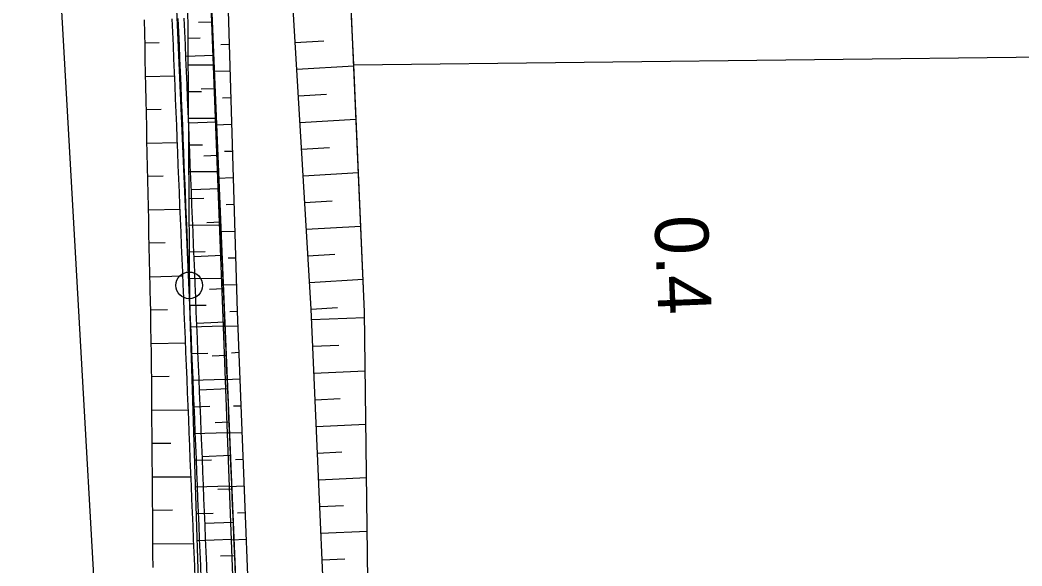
# Model space of a CAD drawing. Extents: x -583721 to -583071, y -1166145 to -1165065.
# Drawn here: x -583239 to -583164, y -1165749.9 to -1165709.1 of the extents above; entities that cross this region are included whole.
import ezdxf

# ---------------------------------------------------------------- set-up
doc = ezdxf.new("R2010")
doc.units = 0
for name, color, linetype in [('01_DOPRAVA', 7, 'Continuous'), ('14', 7, 'Continuous'), ('21', 7, 'Continuous'), ('_Rozpiska', 7, 'Continuous'), ('Kabel_navrh', 7, 'Continuous'), ('KOTY', 7, 'Continuous'), ('Popis cest', 7, 'Continuous'), ('Popis PP', 7, 'Continuous'), ('Rámy', 7, 'Continuous'), ('Trojúhelniky', 7, 'Continuous')]:
    doc.layers.add(name, color=color, linetype=linetype)

msp = doc.modelspace()

# ---------------------------------------------------------------- linework, layer by layer
at = {"layer": '01_DOPRAVA'}
msp.add_line((-583214.03, -1165712.42), (-583111.31, -1165711.19), dxfattribs=at)
for points in [[(-583374.25, -1165656.58), (-583351.23, -1165657.59), (-583331.17, -1165652.35), (-583245.16, -1165665.31), (-583236.84, -1165691.62), (-583230.99, -1165795.18)], [(-583214.03, -1165712.42), (-583215.79, -1165675.68), (-583216.29, -1165664.24)], [(-583228.69, -1165666.2), (-583226.21, -1165672.99), (-583225.84, -1165679.92), (-583220.97, -1165796.08), (-583216.51, -1165909.44), (-583213.19, -1165995.13), (-583203.41, -1165993.97)], [(-583206.76, -1165905.62), (-583208.9, -1165862.71), (-583209.34, -1165848.45), (-583210.45, -1165834.4), (-583212.79, -1165765.14), (-583213.22, -1165730.9), (-583214.03, -1165712.42)]]:
    msp.add_lwpolyline(points, dxfattribs=at)
at = {"layer": '14'}
for p, q in [((-583225.654, -1165709.223), (-583224.613, -1165709.18)), ((-583228.596, -1165710.756), (-583229.657, -1165710.779)), ((-583226.593, -1165711.764), (-583224.509, -1165711.678)), ((-583229.604, -1165713.278), (-583227.434, -1165713.232)), ((-583225.447, -1165714.219), (-583224.404, -1165714.176)), ((-583228.442, -1165715.754), (-583229.552, -1165715.777)), ((-583226.389, -1165716.759), (-583224.299, -1165716.674)), ((-583229.499, -1165718.277), (-583227.229, -1165718.229)), ((-583225.24, -1165719.214), (-583224.194, -1165719.172)), ((-583228.287, -1165720.752), (-583229.446, -1165720.776)), ((-583226.184, -1165721.755), (-583224.09, -1165721.669)), ((-583229.394, -1165723.276), (-583227.025, -1165723.226)), ((-583225.033, -1165724.21), (-583223.985, -1165724.167)), ((-583228.132, -1165725.749), (-583229.341, -1165725.775)), ((-583225.98, -1165726.751), (-583223.88, -1165726.665)), ((-583229.285, -1165728.275), (-583226.82, -1165728.22)), ((-583224.826, -1165729.206), (-583223.775, -1165729.163)), ((-583227.974, -1165730.749), (-583229.231, -1165730.774)), ((-583225.775, -1165731.747), (-583223.671, -1165731.661)), ((-583229.186, -1165733.274), (-583226.615, -1165733.235)), ((-583224.619, -1165734.202), (-583223.566, -1165734.158)), ((-583227.834, -1165735.76), (-583229.155, -1165735.773)), ((-583225.57, -1165736.743), (-583223.461, -1165736.656)), ((-583229.136, -1165738.273), (-583226.409, -1165738.253)), ((-583224.412, -1165739.197), (-583223.357, -1165739.154)), ((-583227.712, -1165740.763), (-583229.117, -1165740.773)), ((-583225.366, -1165741.738), (-583223.252, -1165741.652)), ((-583229.098, -1165743.273), (-583226.205, -1165743.251)), ((-583224.205, -1165744.193), (-583223.147, -1165744.15)), ((-583227.591, -1165745.762), (-583229.08, -1165745.773)), ((-583225.161, -1165746.734), (-583223.042, -1165746.648)), ((-583229.061, -1165748.273), (-583226, -1165748.25)), ((-583223.998, -1165749.189), (-583222.938, -1165749.145))]:
    msp.add_line(p, q, dxfattribs=at)
at = {"layer": '21'}
for points in [[(-583222.868, -1165750.8), (-583222.91, -1165749.801), (-583222.952, -1165748.802), (-583222.994, -1165747.803), (-583223.036, -1165746.804), (-583223.078, -1165745.805), (-583223.12, -1165744.806), (-583223.162, -1165743.806), (-583223.203, -1165742.807), (-583223.245, -1165741.808), (-583223.287, -1165740.809), (-583223.329, -1165739.81), (-583223.371, -1165738.811), (-583223.413, -1165737.812), (-583223.455, -1165736.813), (-583223.497, -1165735.813), (-583223.539, -1165734.814), (-583223.58, -1165733.815), (-583223.622, -1165732.816), (-583223.664, -1165731.817), (-583223.706, -1165730.818), (-583223.71, -1165730.73), (-583223.748, -1165729.819), (-583223.775, -1165729.165), (-583223.79, -1165728.82), (-583223.832, -1165727.82), (-583223.874, -1165726.821), (-583223.916, -1165725.822), (-583223.957, -1165724.823), (-583223.999, -1165723.824), (-583224.041, -1165722.825), (-583224.083, -1165721.826), (-583224.125, -1165720.827), (-583224.167, -1165719.827), (-583224.209, -1165718.828), (-583224.251, -1165717.829), (-583224.254, -1165717.746), (-583224.293, -1165716.83), (-583224.334, -1165715.831), (-583224.376, -1165714.832), (-583224.418, -1165713.833), (-583224.46, -1165712.834), (-583224.502, -1165711.834), (-583224.544, -1165710.835), (-583224.586, -1165709.836), (-583224.628, -1165708.837)], [(-583229.047, -1165750.052), (-583229.055, -1165749.052), (-583229.062, -1165748.051), (-583229.07, -1165747.051), (-583229.078, -1165746.05), (-583229.085, -1165745.05), (-583229.093, -1165744.049), (-583229.1, -1165743.049), (-583229.108, -1165742.048), (-583229.115, -1165741.048), (-583229.123, -1165740.047), (-583229.13, -1165739.047), (-583229.138, -1165738.046), (-583229.146, -1165737.046), (-583229.153, -1165736.045), (-583229.161, -1165735.044), (-583229.173, -1165734.044), (-583229.19, -1165733.044), (-583229.208, -1165732.044), (-583229.226, -1165731.044), (-583229.227, -1165730.956), (-583229.244, -1165730.044), (-583229.259, -1165729.389), (-583229.267, -1165729.044), (-583229.29, -1165728.044), (-583229.313, -1165727.044), (-583229.335, -1165726.044), (-583229.357, -1165725.044), (-583229.378, -1165724.044), (-583229.399, -1165723.044), (-583229.42, -1165722.044), (-583229.441, -1165721.044), (-583229.462, -1165720.044), (-583229.483, -1165719.044), (-583229.504, -1165718.044), (-583229.506, -1165717.961), (-583229.525, -1165717.044), (-583229.546, -1165716.044), (-583229.567, -1165715.044), (-583229.588, -1165714.044), (-583229.609, -1165713.044), (-583229.63, -1165712.044), (-583229.651, -1165711.044), (-583229.672, -1165710.044), (-583229.693, -1165709.045)], [(-583225.891, -1165750.924), (-583225.932, -1165749.925), (-583225.972, -1165748.926), (-583226.013, -1165747.927), (-583226.054, -1165746.927), (-583226.095, -1165745.928), (-583226.136, -1165744.929), (-583226.177, -1165743.93), (-583226.218, -1165742.931), (-583226.259, -1165741.932), (-583226.3, -1165740.932), (-583226.341, -1165739.933), (-583226.382, -1165738.934), (-583226.422, -1165737.935), (-583226.463, -1165736.936), (-583226.504, -1165735.937), (-583226.545, -1165734.937), (-583226.586, -1165733.938), (-583226.627, -1165732.939), (-583226.668, -1165731.94), (-583226.709, -1165730.941), (-583226.712, -1165730.853), (-583226.75, -1165729.942), (-583226.776, -1165729.288), (-583226.791, -1165728.942), (-583226.831, -1165727.943), (-583226.872, -1165726.944), (-583226.913, -1165725.945), (-583226.954, -1165724.946), (-583226.995, -1165723.947), (-583227.036, -1165722.947), (-583227.077, -1165721.948), (-583227.118, -1165720.949), (-583227.159, -1165719.95), (-583227.2, -1165718.951), (-583227.241, -1165717.952), (-583227.244, -1165717.868), (-583227.281, -1165716.952), (-583227.322, -1165715.953), (-583227.363, -1165714.954), (-583227.404, -1165713.955), (-583227.445, -1165712.956), (-583227.486, -1165711.957), (-583227.527, -1165710.957), (-583227.568, -1165709.958), (-583227.609, -1165708.959)], [(-583224.991, -1165750.887), (-583225.032, -1165749.888), (-583225.073, -1165748.889), (-583225.114, -1165747.89), (-583225.155, -1165746.891), (-583225.196, -1165745.891), (-583225.237, -1165744.892), (-583225.278, -1165743.893), (-583225.319, -1165742.894), (-583225.36, -1165741.895), (-583225.4, -1165740.896), (-583225.441, -1165739.896), (-583225.482, -1165738.897), (-583225.523, -1165737.898), (-583225.564, -1165736.899), (-583225.605, -1165735.9), (-583225.646, -1165734.901), (-583225.687, -1165733.901), (-583225.728, -1165732.902), (-583225.769, -1165731.903), (-583225.81, -1165730.904), (-583225.813, -1165730.817), (-583225.85, -1165729.905), (-583225.877, -1165729.251), (-583225.891, -1165728.906), (-583225.932, -1165727.906), (-583225.973, -1165726.907), (-583226.014, -1165725.908), (-583226.055, -1165724.909), (-583226.096, -1165723.91), (-583226.137, -1165722.911), (-583226.178, -1165721.911), (-583226.219, -1165720.912), (-583226.259, -1165719.913), (-583226.3, -1165718.914), (-583226.341, -1165717.915), (-583226.345, -1165717.831), (-583226.382, -1165716.916), (-583226.423, -1165715.916), (-583226.464, -1165714.917), (-583226.505, -1165713.918), (-583226.546, -1165712.919), (-583226.587, -1165711.92), (-583226.628, -1165710.921), (-583226.669, -1165709.922), (-583226.709, -1165708.922)]]:
    msp.add_lwpolyline(points, dxfattribs=at)
at = {"layer": '_Rozpiska'}
for points in [[(-583226.42, -1165710.41), (-583225.52, -1165710.4)], [(-583223.35, -1165710.89), (-583223.97, -1165710.91)], [(-583218.41, -1165710.75), (-583216.27, -1165710.62)], [(-583226.41, -1165712.41), (-583224.54, -1165712.4)], [(-583218.29, -1165712.74), (-583214.03, -1165712.49)], [(-583223.29, -1165712.89), (-583224.52, -1165712.92)], [(-583226.4, -1165714.41), (-583225.43, -1165714.4)], [(-583218.17, -1165714.74), (-583216.06, -1165714.61)], [(-583223.23, -1165714.89), (-583223.84, -1165714.9)], [(-583226.38, -1165716.41), (-583224.39, -1165716.4)], [(-583223.17, -1165716.89), (-583224.37, -1165716.92)], [(-583218.06, -1165716.73), (-583213.86, -1165716.48)], [(-583226.37, -1165718.41), (-583225.34, -1165718.4)], [(-583223.11, -1165718.89), (-583223.7, -1165718.9)], [(-583217.94, -1165718.73), (-583215.85, -1165718.61)], [(-583226.36, -1165720.41), (-583224.24, -1165720.4)], [(-583217.82, -1165720.73), (-583213.68, -1165720.48)], [(-583223.05, -1165720.88), (-583224.22, -1165720.92)], [(-583226.34, -1165722.41), (-583225.25, -1165722.4)], [(-583223, -1165722.88), (-583223.57, -1165722.9)], [(-583217.7, -1165722.72), (-583215.64, -1165722.6)], [(-583226.33, -1165724.41), (-583224.08, -1165724.4)], [(-583217.58, -1165724.72), (-583213.5, -1165724.48)], [(-583222.94, -1165724.88), (-583224.06, -1165724.92)], [(-583226.32, -1165726.41), (-583225.16, -1165726.4)], [(-583217.46, -1165726.72), (-583215.44, -1165726.6)], [(-583222.88, -1165726.88), (-583223.43, -1165726.9)], [(-583226.3, -1165728.41), (-583223.93, -1165728.39)], [(-583222.82, -1165728.88), (-583223.91, -1165728.91)], [(-583217.34, -1165728.71), (-583213.33, -1165728.47)], [(-583226.29, -1165730.41), (-583225.07, -1165730.4)], [(-583217.22, -1165730.71), (-583215.23, -1165730.59)], [(-583222.76, -1165730.88), (-583223.3, -1165730.9)], [(-583217.19, -1165731.49), (-583213.21, -1165731.32)], [(-583226.24, -1165732.03), (-583223.79, -1165731.95)], [(-583222.72, -1165731.97), (-583223.79, -1165732.01)], [(-583217.1, -1165733.49), (-583215.14, -1165733.4)], [(-583226.18, -1165734.03), (-583224.95, -1165733.99)], [(-583222.64, -1165733.96), (-583223.18, -1165733.99)], [(-583217.01, -1165735.49), (-583213.16, -1165735.32)], [(-583226.11, -1165736.02), (-583223.64, -1165735.95)], [(-583222.56, -1165735.96), (-583223.64, -1165736.01)], [(-583226.05, -1165738.02), (-583224.81, -1165737.98)], [(-583222.48, -1165737.96), (-583223.03, -1165737.98)], [(-583216.92, -1165737.49), (-583215.03, -1165737.4)], [(-583216.83, -1165739.49), (-583213.11, -1165739.32)], [(-583225.99, -1165740.02), (-583223.49, -1165739.94)], [(-583222.41, -1165739.96), (-583223.49, -1165740)], [(-583216.74, -1165741.48), (-583214.92, -1165741.4)], [(-583225.93, -1165742.02), (-583224.67, -1165741.98)], [(-583222.33, -1165741.96), (-583222.87, -1165741.98)], [(-583216.65, -1165743.48), (-583213.06, -1165743.32)], [(-583225.87, -1165744.02), (-583223.34, -1165743.94)], [(-583222.25, -1165743.96), (-583223.34, -1165744)], [(-583216.57, -1165745.48), (-583214.8, -1165745.4)], [(-583225.8, -1165746.02), (-583224.54, -1165745.98)], [(-583222.17, -1165745.96), (-583222.72, -1165745.98)], [(-583216.48, -1165747.48), (-583213.01, -1165747.32)], [(-583225.74, -1165748.02), (-583223.2, -1165747.94)], [(-583222.09, -1165747.95), (-583223.19, -1165748)], [(-583216.39, -1165749.48), (-583214.69, -1165749.4)]]:
    msp.add_lwpolyline(points, dxfattribs=at)
at = {"layer": 'Kabel_navrh'}
msp.add_lwpolyline([(-583226.29, -1165730.41), (-583227.5, -1165703.14), (-583228.25, -1165673.5)], dxfattribs=at)
at = {"layer": 'KOTY'}
msp.add_lwpolyline([(-583225.441, -1165750.906), (-583225.482, -1165749.906), (-583225.523, -1165748.907), (-583225.564, -1165747.908), (-583225.605, -1165746.909), (-583225.646, -1165745.91), (-583225.686, -1165744.911), (-583225.727, -1165743.911), (-583225.768, -1165742.912), (-583225.809, -1165741.913), (-583225.85, -1165740.914), (-583225.891, -1165739.915), (-583225.932, -1165738.916), (-583225.973, -1165737.916), (-583226.014, -1165736.917), (-583226.055, -1165735.918), (-583226.096, -1165734.919), (-583226.136, -1165733.92), (-583226.177, -1165732.921), (-583226.218, -1165731.922), (-583226.259, -1165730.922), (-583226.263, -1165730.835), (-583226.3, -1165729.923), (-583226.327, -1165729.269), (-583226.341, -1165728.924), (-583226.382, -1165727.925), (-583226.423, -1165726.926), (-583226.464, -1165725.927), (-583226.505, -1165724.927), (-583226.545, -1165723.928), (-583226.586, -1165722.929), (-583226.627, -1165721.93), (-583226.668, -1165720.931), (-583226.709, -1165719.932), (-583226.75, -1165718.932), (-583226.791, -1165717.933), (-583226.794, -1165717.85), (-583226.832, -1165716.934), (-583226.873, -1165715.935), (-583226.914, -1165714.936), (-583226.955, -1165713.937), (-583226.995, -1165712.937), (-583227.036, -1165711.938), (-583227.077, -1165710.939), (-583227.118, -1165709.94), (-583227.159, -1165708.941)], dxfattribs=at)
at = {"layer": 'Popis cest'}
for points in [[(-583214.565, -1166024.741), (-583215.84, -1165999.86), (-583216.56, -1165980.47), (-583218.74, -1165935.28), (-583219.93, -1165903.85), (-583222.02, -1165858.12), (-583222.68, -1165835.28), (-583223.83, -1165795.43), (-583225.18, -1165766.01), (-583226.29, -1165730.41), (-583226.47, -1165703.12), (-583228.25, -1165673.5)], [(-583202.046, -1166023.279), (-583203.28, -1165999.31), (-583203.79, -1165978.24), (-583205.99, -1165934.1), (-583206.83, -1165909.26), (-583206.76, -1165905.62), (-583208.9, -1165862.71), (-583209.34, -1165848.45), (-583210.45, -1165834.4), (-583212.79, -1165765.14), (-583213.22, -1165730.9), (-583214.43, -1165703.46)]]:
    msp.add_lwpolyline(points, dxfattribs=at)
at = {"layer": 'Popis PP'}
for points in [[(-583205.384, -1166023.669), (-583206.37, -1165999.45), (-583206.99, -1165978.09), (-583208.8, -1165934.4), (-583209.98, -1165909.96), (-583210.18, -1165905.46), (-583211.89, -1165862.15), (-583212.92, -1165834.81), (-583214.61, -1165795.62), (-583215.68, -1165765.46), (-583217.22, -1165730.71), (-583218.84, -1165703.6), (-583219.86, -1165675.86), (-583220.15, -1165659.61)], [(-583225.03, -1165669.36), (-583224.72, -1165676.77), (-583223.57, -1165703.33), (-583222.76, -1165730.88), (-583221.39, -1165765.94), (-583219.92, -1165795.75), (-583218.23, -1165835.3), (-583217.57, -1165858.89), (-583215.65, -1165904.71), (-583214.33, -1165934.9), (-583212.44, -1165979.07), (-583211.41, -1165999.47), (-583210.642, -1166024.283)]]:
    msp.add_lwpolyline(points, dxfattribs=at)
at = {"layer": 'Rámy'}
msp.add_lwpolyline([(-583225.84, -1165679.92), (-583224.89, -1165703.34), (-583223.84, -1165730.71), (-583222.52, -1165765.99), (-583221.05, -1165795.86), (-583219.53, -1165835.39), (-583218.74, -1165858.37), (-583216.69, -1165904.53), (-583215.95, -1165934.96), (-583213.79, -1165980.28), (-583213.02, -1165999.42)], dxfattribs=at)
at = {"layer": 'Trojúhelniky'}
msp.add_circle((-583226.341, -1165728.924), 1, dxfattribs=at)
msp.add_circle((-583226.341, -1165728.924), 1, dxfattribs=at)

# ---------------------------------------------------------------- texts
msp.add_text('0.4', height=4, rotation=272.3443, dxfattribs=at).set_placement((-583191.524, -1165723.749))

doc.saveas('drawing.dxf')
